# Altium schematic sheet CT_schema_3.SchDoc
size 313 x 185 mm
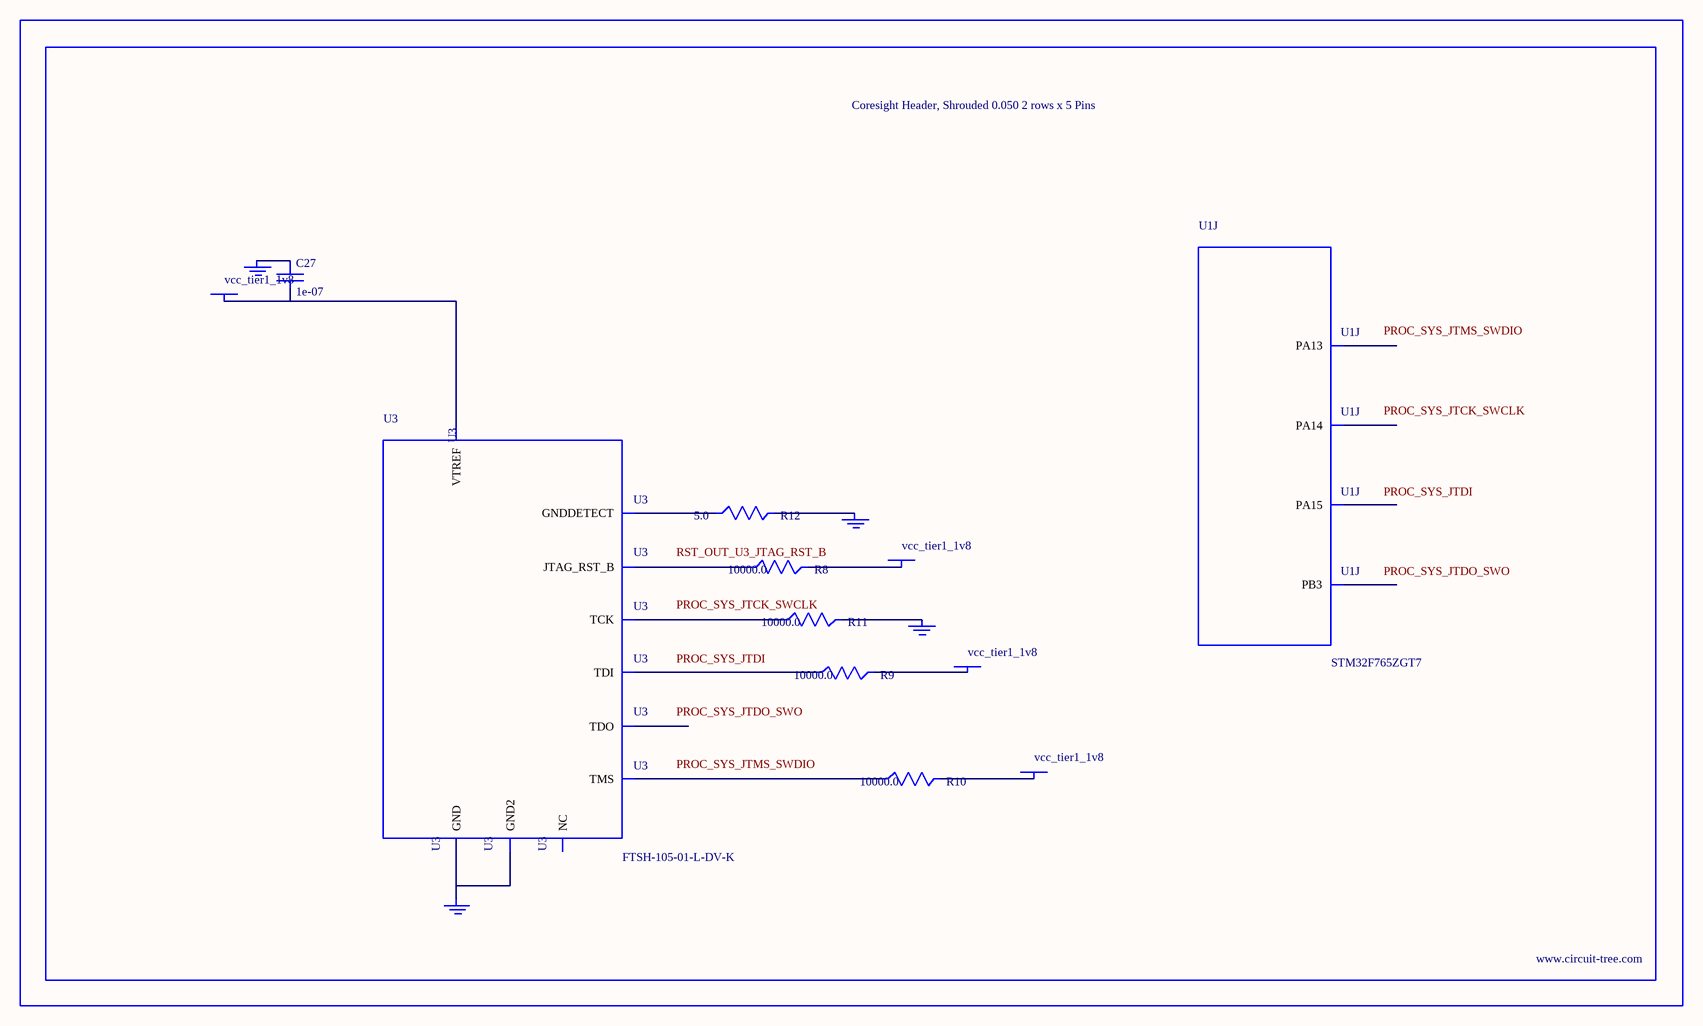
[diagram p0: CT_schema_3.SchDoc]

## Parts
BORDER2  (no value)
C27  1e-07  [C0402]
GND_INSTANCE_2_0  (no value)
GND_INSTANCE_2_1  (no value)
GND_INSTANCE_2_2  (no value)
GND_INSTANCE_2_3  (no value)
POWER_INSTANCE_2_0  vcc_tier1_1v8
POWER_INSTANCE_2_1  vcc_tier1_1v8
POWER_INSTANCE_2_2  vcc_tier1_1v8
POWER_INSTANCE_2_3  vcc_tier1_1v8
R8  10000.0  [R0603]
R9  10000.0  [R0603]
R10  10000.0  [R0603]
R11  10000.0  [R0603]
R12  5.0  [R0603]
U1  STM32F765ZGT7  [LQFP144]  (part J of 11)
U3  FTSH-105-01-L-DV-K  [SAMTEC_FTSH-105-01-L-DV-K]

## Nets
NetC27_1: C27.1 GND_INSTANCE_2_0.0(GND)
NetC27_2: C27.2 POWER_INSTANCE_2_0.0(PWR) U3.1(VTREF)
NetGND_INSTANCE_2_1_0: GND_INSTANCE_2_1.0(GND) R11.2
NetGND_INSTANCE_2_2_0: GND_INSTANCE_2_2.0(GND) R12.2
NetGND_INSTANCE_2_3_0: GND_INSTANCE_2_3.0(GND) U3.3(GND) U3.5(GND2)
NetPOWER_INSTANCE_2_1_0: POWER_INSTANCE_2_1.0(PWR) R10.2
NetPOWER_INSTANCE_2_2_0: POWER_INSTANCE_2_2.0(PWR) R9.2
NetPOWER_INSTANCE_2_3_0: POWER_INSTANCE_2_3.0(PWR) R8.2
NetR8_1: R8.1 U3.10(JTAG_RST_B)
NetR9_1: R9.1 U3.8(TDI)
NetR10_1: R10.1 U3.2(TMS)
NetR11_1: R11.1 U3.4(TCK)
NetR12_1: R12.1 U3.9(GNDDETECT)

Not connected (* = marked no-connect by the designer): U1 105(PA13) 109(PA14) 110(PA15) 133(PB3); U3 6(TDO) 7(NC)

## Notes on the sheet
- Labels drawn without touching a wire or pin: PROC_SYS_JTCK_SWCLK, PROC_SYS_JTDI, PROC_SYS_JTDO_SWO, PROC_SYS_JTMS_SWDIO, RST_OUT_U3_JTAG_RST_B

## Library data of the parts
BORDER2 = BORDER_PAGE2
C27 = C0402C104K3RACTU
GND_INSTANCE_2_0-GND_INSTANCE_2_3 = GND
POWER_INSTANCE_2_0-POWER_INSTANCE_2_3 = PWR
R8-R11 = RC0603JR-0710KL
R12 = ERJ-3GEYJ5R1V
